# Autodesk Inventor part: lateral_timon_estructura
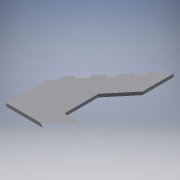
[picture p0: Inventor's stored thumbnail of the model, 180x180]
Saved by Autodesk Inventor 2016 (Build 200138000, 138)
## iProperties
Created: 2017-06
Part Number: lateral_timon_estructura
Material: Generic
Document SubType Name: Modeling
Designer: laboratorioesan
Density: 1 g/cm^3
Appearance: Default
Author: laboratorioesan
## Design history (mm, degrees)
sketch "Sketch1"
  geometry: L1 (0, 0)-(32.036, 38.389) reference; L2 (0, 0)-(11.901, -9.931) reference; L3 (43.937, 28.458)-(11.901, -9.931) reference; L4 (32.036, 38.389)-(43.937, 28.458) reference; L5 (-64.072, -76.777)-(-32.036, -38.389) reference; L6 (-64.072, -76.777)-(-52.172, -86.709) reference; L7 (-20.136, -48.32)-(-52.172, -86.709) reference; L8 (-32.036, -38.389)-(-20.136, -48.32) reference; L9 (-128.144, -153.555)-(-96.108, -115.166) reference; L10 (-128.144, -153.555)-(-116.244, -163.486) reference; L11 (-84.208, -125.097)-(-116.244, -163.486) reference; L12 (-96.108, -115.166)-(-84.208, -125.097) reference; L13 (-198.623, -238.01)-(-166.587, -199.621) reference; L14 (-198.623, -238.01)-(-186.723, -247.941) reference; L15 (-154.687, -209.552)-(-186.723, -247.941) reference; L16 (-166.587, -199.621)-(-154.687, -209.552) reference; L17 (-0.435, -485.534)-(49.565, -485.534) reference; L18 (-0.435, -485.534)-(-0.435, -501.034) reference; L19 (49.565, -501.034)-(-0.435, -501.034) reference; L20 (49.565, -485.534)-(49.565, -501.034) reference; L21 (-100.435, -485.534)-(-50.435, -485.534) reference; L22 (-100.435, -485.534)-(-100.435, -501.034) reference; L23 (-50.435, -501.034)-(-100.435, -501.034) reference; L24 (-50.435, -485.534)-(-50.435, -501.034) reference; L25 (-200.44, -485.534)-(-150.44, -485.534) reference; L26 (-200.44, -485.534)-(-200.44, -501.034) reference; L27 (-150.44, -501.034)-(-200.44, -501.034) reference; L28 (-150.44, -485.534)-(-150.44, -501.034) reference; L29 (-220.44, -485.534)-(69.565, -485.534); L30 (69.565, -485.534)-(69.565, 59.169); L31 (69.565, 59.169)-(-220.44, -288.345); L32 (-220.44, -288.345)-(-220.44, -485.534)
  constraints: 8 end point, 1 collinear, 1 horizontal, 1 parallel, 1 perpendicular, 1 point on line
  dimensions: "d0" = 20 distance of L25.start L29.start; "d1" = 20 distance of L29.end L17.end
extrude "Extrusion1" new body sketch "Sketch1" distance "d2" = 15.5; taper "d3" = 0 deg
sketch "Sketch2"
  geometry: L1 (-96.108, -115.166)-(-128.144, -153.555) reference; L2 (-128.144, -153.555)-(-116.244, -163.486) reference; L3 (-116.244, -163.486)-(-154.687, -209.552) reference; L4 (-154.687, -209.552)-(-166.587, -199.621) reference; L5 (-166.587, -199.621)-(-198.623, -238.01) reference; L6 (-198.623, -238.01)-(-186.723, -247.941) reference; L7 (-186.723, -247.941)-(-220.44, -288.345) reference; L8 (-220.44, -288.345)-(-220.44, -485.534) reference; L9 (-220.44, -485.534)-(69.565, -485.534) reference; L10 (69.565, -485.534)-(69.565, 59.169) reference; L11 (69.565, 59.169)-(43.937, 28.458) reference; L12 (43.937, 28.458)-(32.036, 38.389) reference; L13 (32.036, 38.389)-(0, 0) reference; L14 (0, 0)-(11.901, -9.931) reference; L15 (11.901, -9.931)-(-20.136, -48.32) reference; L16 (-20.136, -48.32)-(-32.036, -38.389) reference; L17 (-32.036, -38.389)-(-64.072, -76.777) reference; L18 (-64.072, -76.777)-(-52.172, -86.709) reference; L19 (-52.172, -86.709)-(-84.208, -125.097) reference; L20 (-84.208, -125.097)-(-96.108, -115.166) reference; L21 (69.565, -485.534)-(69.565, 59.169) reference; L22 (69.565, -96.906)-(-30.435, -216.736); L23 (-30.435, -216.736)-(-30.435, -385.534); L24 (-30.435, -385.534)-(69.565, -385.534); 1 further point
  constraints: 6 end point, 2 parallel, 2 point on line, 1 perpendicular
  dimensions: "d4" = 100 distance between parallel lines of L9 L24; "d5" = 100 distance between parallel lines of L19 L22; "d6" = 100 distance between parallel lines of L10 L23
extrude "Extrusion2" cut sketch "Sketch2" distance "d7" = 15.5; taper "d8" = 0 deg
body "Solid1"
node "Reference1"
node "Reference2"
node "Reference3"
node "Reference4"
node "Reference5"
node "Reference6"
node "Reference7"
node "Reference8"
node "Projected Loop1"
